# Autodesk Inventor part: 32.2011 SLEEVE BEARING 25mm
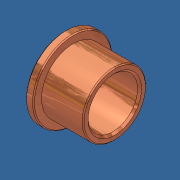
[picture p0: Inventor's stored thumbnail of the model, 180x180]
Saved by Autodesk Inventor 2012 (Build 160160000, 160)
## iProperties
Created: 2016-09
Part Number: 32.2011 SLEEVE BEARING 25mm
Material: Default
Document SubType Name: Modeling
Designer: Admin
Density: 1 g/cm^3
Author: Admin
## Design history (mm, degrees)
feature "Base1"
body "Solid1"
